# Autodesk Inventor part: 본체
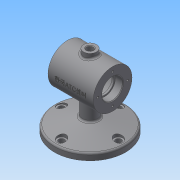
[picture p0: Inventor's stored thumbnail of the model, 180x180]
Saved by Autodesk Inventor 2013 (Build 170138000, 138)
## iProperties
Created: 2018-12
Part Number: 본체
Material: 일반
Document SubType Name: Modeling
Designer: Gpr
Density: 1 g/cm^3
Author: Gpr
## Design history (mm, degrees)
sketch "스케치1"
  geometry: C1 r 55 at (0, 0); 1 further point
  constraints: 1 centre point, 1 coincident
  dimensions: "d0" = 110 diameter of C1
extrude "돌출1" new body sketch "스케치1" distance "d1" = 10; taper "d2" = 0 deg
sketch "스케치2"
  geometry: L1 (-35, 105)-(35, 105); L2 (35, 105)-(35, 91); L3 (35, 91)-(23, 91); L4 (23, 91)-(23, 89); L5 (23, 89)-(20, 89); L6 (20, 89)-(20, 100); L7 (20, 100)-(-20, 100); L8 (-20, 100)-(-20, 89); L9 (-20, 89)-(-23, 89); L10 (-23, 89)-(-23, 91); L11 (-23, 91)-(-35, 91); L12 (-35, 91)-(-35, 105); L13 (-35, 75)-(35, 75); 4 further points
  constraints: 26 end point, 7 horizontal, 6 vertical, 5 vertical alignment, 3 midpoint, 2 horizontal alignment
  dimensions: "d3" = 28 diameter of L9 L13; "d5" = 32 diameter of L11 L13; "d6" = 50 diameter of L7 L13; "d7" = 40 distance of L6.end L7.end; "d8" = 3 distance of L8.end L9.end; "d9" = 12 distance of L10.end L11.end; "d10" = 12 distance of L2.end L3.end; "d11" = 75 distance of point (0, 0) point (0, 75); "d12" = 60 diameter of L1 L13
revolve "회전1" sketch "스케치2" stored, may be unused: angle "d13" = 90 deg
sketch "스케치6"
  geometry: C1 r 12 at (0, 0); 1 further point
  constraints: 1 centre point, 1 coincident
  dimensions: "d14" = 24 diameter of C1
extrude "돌출2" join sketch "스케치6" stored distance "d15" = 15; taper "d16" = 0 deg
sketch "스케치7"
  geometry: C1 r 55 at (0, 0) reference; 1 further point
extrude "돌출3" join sketch "스케치7" distance "d17" = 15; taper "d18" = -75 deg
sketch "스케치8"
  geometry: C1 r 30 at (0, 0) reference; 2 further points
  constraints: 1 vertical alignment
  dimensions: "d19" = 23 distance of C1.centre point (0, 23)
hole "구멍1" sketch "스케치8" at (0, 23) diameter "d20" = 3.242; stored, may be unused: countersink angle "d24" = 90 deg, drill point angle "d26" = 118 deg; dims "d21" = 8, "d22" = 4, "d23" = 2, "d25" = 10
fillet "모깎기1" dims "d30" = 0.3
chamfer "모따기1" distance "d31" = 1; stored, may be unused: second distance "d32" = 2, angle "d33" = 45 deg
node "작업 평면1"
sketch "스케치9"
  geometry: C1 r 10 at (0, 0); 1 further point
  constraints: 1 centre point, 1 coincident
  dimensions: "d35" = 20 diameter of C1
extrude "돌출4" join sketch "스케치9" stored distance "d36" = 15; taper "d37" = 0 deg
hole "구멍2" diameter "d40" = 10; stored, may be unused: countersink angle "d44" = 90 deg, drill point angle "d46" = 0 deg; dims "d38" = 10, "d39" = 10, "d41" = 8, "d42" = 4, "d43" = 2, "d45" = 10
chamfer "모따기2" distance "d47" = 1; stored, may be unused: second distance "d48" = 2, angle "d49" = 45 deg
sketch "스케치10"
  geometry: 2 further points
  constraints: 1 vertical alignment
  dimensions: "d50" = 44 distance of point (0, 0) point (0, 44)
hole "구멍3" sketch "스케치10" at (0, 44) diameter "d51" = 9; stored, may be unused: countersink angle "d55" = 90 deg, drill point angle "d57" = 0 deg; dims "d52" = 8, "d53" = 4, "d54" = 2, "d56" = 10
hole "구멍4" diameter "d60" = 14; stored, may be unused: countersink angle "d64" = 90 deg, drill point angle "d66" = 0 deg; dims "d58" = 10, "d59" = 10, "d61" = 8, "d62" = 4, "d63" = 2, "d65" = 10
node "작업 평면2"
sketch "스케치11"
  geometry: L1 (-35, 45)-(-35, 105) reference; L2 (-35, 105)-(35, 105) reference; 2 further points
  constraints: 1 other
  dimensions: "d71" = 35 distance from line of point (0, 75) L1; "d73" = 30 distance from line of point (0, 75) L2
feature "엠보싱1" sketch "스케치11" dims "d74" = 0.5, "d75" = 0
fillet "모깎기2" dims "d76" = 3
node "솔리드1"
pattern_circular "원형 패턴1" dims angle "d28" = 360 deg
mirror "대칭1"
pattern_circular "원형 패턴2" dims angle "d68" = 360 deg
other parameters: "d34" = -112, "d70" = 71.75
